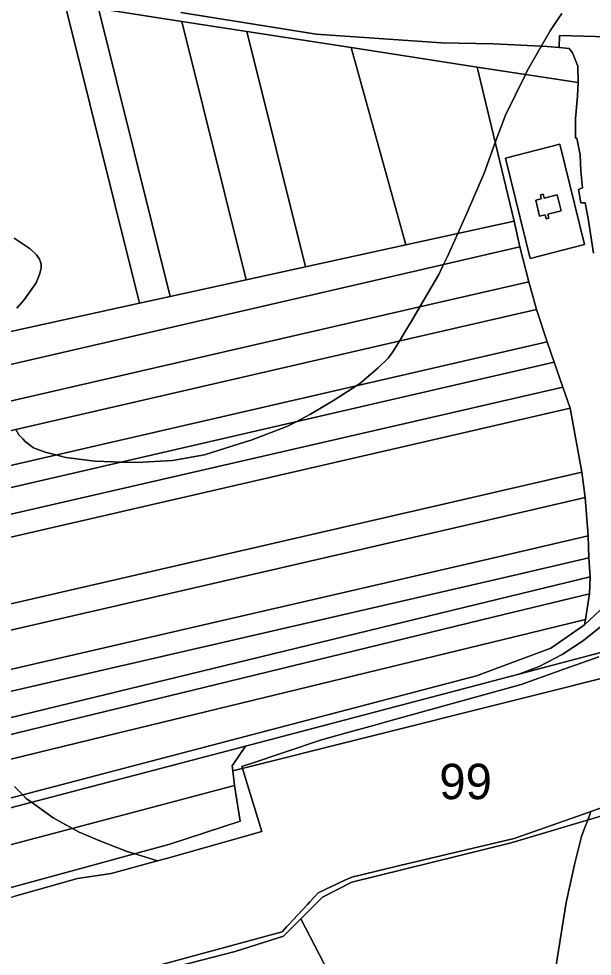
# Model space of a CAD drawing. Extents: x -521939 to -516426, y -1197857 to -1189551.
# Drawn here: x -519336.3 to -519093.3, y -1193402.1 to -1193004.4 of the extents above; entities that cross this region are included whole.
import ezdxf

# ---------------------------------------------------------------- set-up
doc = ezdxf.new("R2010")
doc.units = 0
for name, color, linetype in [('95560013', 7, 'Continuous'), ('95610013', 7, 'Continuous'), ('95620013', 7, 'Continuous'), ('95640013', 7, 'Continuous'), ('95660013', 7, 'Continuous')]:
    doc.layers.add(name, color=color, linetype=linetype)

msp = doc.modelspace()

# ---------------------------------------------------------------- linework, layer by layer
at = {"layer": '95560013'}
for points in [[(-519342.22, -1193137.6), (-519379.4, -1192988.21), (-519316.79, -1192997.86), (-519285.18, -1193125.04)], [(-519316.79, -1192997.86), (-519302.57, -1193000.06), (-519272.23, -1193122.17), (-519285.18, -1193125.04)], [(-519302.57, -1193000.06), (-519267.23, -1193005.51), (-519239.97, -1193115.13), (-519272.23, -1193122.17)], [(-519239.97, -1193115.13), (-519267.23, -1193005.51), (-519239.74, -1193009.74), (-519214.83, -1193109.59)], [(-519214.83, -1193109.59), (-519239.74, -1193009.74), (-519195.48, -1193016.56), (-519172.33, -1193100.26)], [(-519195.48, -1193016.56), (-519142.04, -1193024.85), (-519126.47, -1193090.19), (-519172.33, -1193100.26)], [(-519239.97, -1193115.13), (-519214.83, -1193109.59), (-519172.33, -1193100.26), (-519126.47, -1193090.19), (-519123.99, -1193101.18), (-519170.84, -1193111.98), (-519345.53, -1193152.25), (-519523.43, -1193193.26), (-519526.25, -1193178), (-519492.9, -1193170.62), (-519467.25, -1193165.07), (-519449.34, -1193161.11), (-519428.65, -1193156.57), (-519408.54, -1193152.16), (-519391.66, -1193148.43), (-519367.63, -1193143.15), (-519342.22, -1193137.6), (-519285.18, -1193125.04), (-519272.23, -1193122.17)], [(-519123.99, -1193101.18), (-519120.24, -1193115.95), (-519170.81, -1193127.61), (-519345.68, -1193167.93), (-519520.68, -1193208.28), (-519523.43, -1193193.26), (-519345.53, -1193152.25), (-519170.84, -1193111.98)], [(-519120.24, -1193115.95), (-519116.96, -1193127.76), (-519164.22, -1193138.66), (-519341.25, -1193179.49), (-519518.41, -1193220.35), (-519520.68, -1193208.28), (-519345.68, -1193167.93), (-519170.81, -1193127.61)], [(-519518.41, -1193220.35), (-519341.25, -1193179.49), (-519164.22, -1193138.66), (-519116.96, -1193127.76), (-519112.38, -1193141.37), (-519168.8, -1193154.38), (-519342.31, -1193194.39), (-519515.82, -1193234.4)], [(-519515.82, -1193234.4), (-519342.31, -1193194.39), (-519168.8, -1193154.38), (-519112.38, -1193141.37), (-519109.38, -1193150.03), (-519158.4, -1193161.36), (-519330.9, -1193201.23), (-519514.13, -1193243.58)], [(-519514.13, -1193243.58), (-519330.9, -1193201.23), (-519158.4, -1193161.36), (-519109.38, -1193150.03), (-519105.74, -1193160.59), (-519151.16, -1193171.07), (-519331.67, -1193212.72), (-519512.05, -1193254.34)], [(-519512.05, -1193254.34), (-519331.67, -1193212.72), (-519151.16, -1193171.07), (-519105.74, -1193160.59), (-519102.67, -1193169.53), (-519158.33, -1193182.37), (-519334.24, -1193222.95), (-519510.02, -1193263.5)], [(-519102.67, -1193169.53), (-519097.75, -1193196.73), (-519152.16, -1193209.3), (-519327.38, -1193249.78), (-519502.6, -1193290.26), (-519510.02, -1193263.5), (-519334.24, -1193222.95), (-519158.33, -1193182.37)], [(-519502.6, -1193290.26), (-519327.38, -1193249.78), (-519152.16, -1193209.3), (-519097.75, -1193196.73), (-519096.25, -1193207.51), (-519145.49, -1193218.89), (-519324.45, -1193260.25), (-519498.91, -1193300.57)], [(-519498.91, -1193300.57), (-519324.45, -1193260.25), (-519145.49, -1193218.89), (-519096.25, -1193207.51), (-519095.03, -1193223.76), (-519135.65, -1193233.16), (-519314.81, -1193274.62), (-519492.76, -1193315.8)], [(-519492.76, -1193315.8), (-519314.81, -1193274.62), (-519135.65, -1193233.16), (-519095.03, -1193223.76), (-519094.71, -1193233.1), (-519131.02, -1193241.48), (-519310.1, -1193282.81), (-519488.92, -1193324.08)], [(-519094.71, -1193233.1), (-519094.15, -1193241.05), (-519147.76, -1193254.09), (-519314.51, -1193294.65), (-519483.11, -1193335.66), (-519488.92, -1193324.08), (-519310.1, -1193282.81), (-519131.02, -1193241.48)], [(-519094.15, -1193241.05), (-519094.48, -1193248.3), (-519130.26, -1193257.01), (-519304.97, -1193299.54), (-519479.68, -1193342.07), (-519483.11, -1193335.66), (-519314.51, -1193294.65), (-519147.76, -1193254.09)], [(-519479.68, -1193342.07), (-519304.97, -1193299.54), (-519130.26, -1193257.01), (-519094.48, -1193248.3), (-519096.2, -1193259.2), (-519126.3, -1193266.53), (-519300.33, -1193308.91), (-519474.36, -1193351.29)], [(-519096.2, -1193259.2), (-519096.57, -1193261.51), (-519110.89, -1193271.43), (-519142.38, -1193283.13), (-519283.48, -1193320.18), (-519459.16, -1193366.31), (-519466.55, -1193363.58), (-519474.36, -1193351.29), (-519300.33, -1193308.91), (-519126.3, -1193266.53)], [(-519458.56, -1193374.41), (-519456.94, -1193369.86), (-519284.36, -1193324.57), (-519240.31, -1193313.01), (-519245.94, -1193321.3), (-519245.64, -1193323.44), (-519244.89, -1193329.7), (-519279.58, -1193338.87), (-519451.29, -1193384.26)], [(-519244.89, -1193329.7), (-519242.56, -1193344.82), (-519272.27, -1193354.6), (-519363, -1193379.33), (-519414.21, -1193393.4), (-519436.58, -1193400.77), (-519451.29, -1193384.26), (-519279.58, -1193338.87)]]:
    msp.add_lwpolyline(points, close=True, dxfattribs=at)
at = {"layer": '95610013'}
msp.add_lwpolyline([(-519216.77, -1193386.17), (-519201.14, -1193416.51), (-519380.85, -1193458.26), (-519400.65, -1193437.87), (-519323.14, -1193420.3), (-519244.63, -1193400.06), (-519224.13, -1193393.57)], close=True, dxfattribs=at)
at = {"layer": '95620013'}
for points in [[(-519051.78, -1193263.19), (-519124.36, -1193282.37), (-519115.87, -1193279.15), (-519106.02, -1193274.02), (-519097.04, -1193268.18), (-519089.06, -1193261.77), (-519081.5, -1193254.17), (-519075.4, -1193246.52), (-519067.67, -1193235.07), (-519065.42, -1193233.19), (-519057.96, -1193237.27)], [(-519124.36, -1193282.37), (-519051.78, -1193263.19), (-519049.8, -1193274.26), (-519072.06, -1193279.85), (-519245.64, -1193323.44), (-519245.94, -1193321.3), (-519240.31, -1193313.01)], [(-519049.8, -1193274.26), (-519040.03, -1193304.65), (-519061.29, -1193334.23), (-519127.73, -1193353.98), (-519195.16, -1193370.61), (-519207.67, -1193377.01), (-519216.77, -1193386.17), (-519224.13, -1193393.57), (-519244.63, -1193400.06), (-519323.14, -1193420.3), (-519400.65, -1193437.87), (-519436.58, -1193400.77), (-519414.21, -1193393.4), (-519363, -1193379.33), (-519272.27, -1193354.6), (-519242.56, -1193344.82), (-519244.89, -1193329.7), (-519245.64, -1193323.44), (-519072.06, -1193279.85)]]:
    msp.add_lwpolyline(points, close=True, dxfattribs=at)
at = {"layer": '95640013'}
for points in [[(-519267.67, -1193001.68), (-519210.29, -1193010.83), (-519157.21, -1193014.6), (-519135.18, -1193014.94), (-519126.21, -1193015.42), (-519112.45, -1193016.14), (-519107.3, -1193016.61), (-519103.14, -1193016.99), (-519101.64, -1193018.75), (-519099.43, -1193024.53), (-519099.27, -1193031.44), (-519142.04, -1193024.85), (-519195.48, -1193016.56), (-519239.74, -1193009.74), (-519267.23, -1193005.51), (-519302.57, -1193000.06)], [(-519081.82, -1193012.11), (-519107.14, -1193011.48), (-519107.3, -1193016.61), (-519112.45, -1193016.14), (-519126.21, -1193015.42), (-519135.18, -1193014.94), (-519157.21, -1193014.6), (-519210.29, -1193010.83), (-519267.67, -1193001.68)], [(-519092.79, -1193103.81), (-519094.99, -1193089.06), (-519096.34, -1193082.48), (-519098.12, -1193082.46), (-519099.18, -1193076.82), (-519097.38, -1193076.11), (-519098.14, -1193068.98), (-519098.49, -1193062.14), (-519099.79, -1193055.02), (-519100.47, -1193055.02), (-519100.42, -1193046.7), (-519099.54, -1193037.16), (-519099.27, -1193031.44), (-519099.43, -1193024.53), (-519101.64, -1193018.75), (-519103.14, -1193016.99), (-519107.3, -1193016.61), (-519107.14, -1193011.48), (-519081.82, -1193012.11)], [(-519083.46, -1193249.19), (-519096.57, -1193261.51), (-519096.2, -1193259.2), (-519094.48, -1193248.3), (-519094.15, -1193241.05), (-519094.71, -1193233.1), (-519095.03, -1193223.76), (-519096.25, -1193207.51), (-519097.75, -1193196.73), (-519102.67, -1193169.53), (-519105.74, -1193160.59), (-519109.38, -1193150.03), (-519112.38, -1193141.37), (-519116.96, -1193127.76), (-519120.24, -1193115.95), (-519123.99, -1193101.18), (-519126.47, -1193090.19), (-519142.04, -1193024.85), (-519099.27, -1193031.44), (-519099.54, -1193037.16), (-519100.42, -1193046.7), (-519100.47, -1193055.02), (-519099.79, -1193055.02), (-519098.49, -1193062.14), (-519098.14, -1193068.98), (-519097.38, -1193076.11), (-519099.18, -1193076.82), (-519098.12, -1193082.46), (-519096.34, -1193082.48), (-519094.99, -1193089.06), (-519092.79, -1193103.81)]]:
    msp.add_lwpolyline(points, dxfattribs=at)
for points in [[(-519130.14, -1193063.54), (-519107.08, -1193057.58), (-519096.56, -1193100.18), (-519119.61, -1193106.06)], [(-519130.14, -1193063.54), (-519119.61, -1193106.06), (-519096.56, -1193100.18), (-519107.08, -1193057.58)], [(-519115.28, -1193079.08), (-519114.18, -1193078.8), (-519113.75, -1193080.45), (-519108.18, -1193079.1), (-519106.53, -1193085.86), (-519112.13, -1193087.24), (-519111.74, -1193088.97), (-519112.85, -1193089.23), (-519113.24, -1193087.5), (-519115.62, -1193088.05), (-519117.25, -1193081.31), (-519114.91, -1193080.73)], [(-519114.91, -1193080.73), (-519117.25, -1193081.31), (-519115.62, -1193088.05), (-519113.24, -1193087.5), (-519112.85, -1193089.23), (-519111.74, -1193088.97), (-519112.13, -1193087.24), (-519106.53, -1193085.86), (-519108.18, -1193079.1), (-519113.75, -1193080.45), (-519114.18, -1193078.8), (-519115.28, -1193079.08)], [(-519110.89, -1193271.43), (-519096.57, -1193261.51), (-519083.46, -1193249.19), (-519064.08, -1193221.98), (-519063.8, -1193218.73), (-519061.2, -1193228.34), (-519057.96, -1193237.27), (-519065.42, -1193233.19), (-519067.67, -1193235.07), (-519075.4, -1193246.52), (-519081.5, -1193254.17), (-519089.06, -1193261.77), (-519097.04, -1193268.18), (-519106.02, -1193274.02), (-519115.87, -1193279.15), (-519124.36, -1193282.37), (-519240.31, -1193313.01), (-519284.36, -1193324.57), (-519456.94, -1193369.86), (-519458.56, -1193374.41), (-519466.55, -1193363.58), (-519459.16, -1193366.31), (-519283.48, -1193320.18), (-519142.38, -1193283.13)], [(-519110.84, -1193580.01), (-519128.68, -1193547.96), (-519143.89, -1193520.55), (-519162.86, -1193486.08), (-519175.78, -1193463.01), (-519186.96, -1193442.78), (-519201.14, -1193416.51), (-519216.77, -1193386.17), (-519207.67, -1193377.01), (-519195.16, -1193370.61), (-519127.73, -1193353.98), (-519061.29, -1193334.23), (-519040.03, -1193304.65), (-519037.03, -1193315.32), (-519029.64, -1193352.06), (-519013.6, -1193412.23), (-518995.72, -1193458.59), (-518983.73, -1193485.98), (-518969.16, -1193519.14), (-518956.05, -1193564.77), (-518954.36, -1193589.13), (-519083.02, -1193619.12), (-519102.82, -1193594.23)]]:
    msp.add_lwpolyline(points, close=True, dxfattribs=at)
at = {"layer": '95660013'}
for points in [[(-519106.24, -1193002.19), (-519107.69, -1193004.38), (-519111.1, -1193009.53), (-519115.32, -1193016.87), (-519120.83, -1193026.45), (-519121.6, -1193028), (-519130.11, -1193045.23), (-519134.4, -1193056.9), (-519139.15, -1193069.8), (-519146.33, -1193086.49), (-519150.29, -1193095.42), (-519153.52, -1193102.72), (-519154.86, -1193105.52), (-519156.35, -1193108.64), (-519158.39, -1193112.92), (-519166.34, -1193126.58), (-519169.86, -1193132.62), (-519172.58, -1193137.1), (-519175.05, -1193141.16), (-519177.75, -1193145.6), (-519178.92, -1193147.17), (-519179.83, -1193148.39), (-519184.12, -1193152.56), (-519192, -1193159.28), (-519193.12, -1193159.99), (-519203.01, -1193166.24), (-519212.64, -1193172.15), (-519218.76, -1193175.31), (-519222.72, -1193177.36), (-519237.9, -1193183.16), (-519240.32, -1193183.91), (-519257.61, -1193189.3), (-519271.17, -1193191.74), (-519286.24, -1193192.66), (-519292.89, -1193192.45), (-519296.16, -1193192.34), (-519304.09, -1193192.09), (-519316.38, -1193190.46), (-519320.65, -1193189.39), (-519325.19, -1193188.26), (-519330.05, -1193186.41), (-519333.65, -1193183.74), (-519334.67, -1193182.63), (-519336.31, -1193180.84), (-519337.56, -1193178.64)], [(-519337.56, -1193178.64), (-519336.31, -1193180.84), (-519334.67, -1193182.63), (-519333.65, -1193183.74), (-519330.05, -1193186.41), (-519325.19, -1193188.26), (-519320.65, -1193189.39), (-519316.38, -1193190.46), (-519304.09, -1193192.09), (-519296.16, -1193192.34), (-519292.89, -1193192.45), (-519286.24, -1193192.66), (-519271.17, -1193191.74), (-519257.61, -1193189.3), (-519240.32, -1193183.91), (-519237.9, -1193183.16), (-519222.72, -1193177.36), (-519218.76, -1193175.31), (-519212.64, -1193172.15), (-519203.01, -1193166.24), (-519193.12, -1193159.99), (-519192, -1193159.28), (-519184.12, -1193152.56), (-519179.83, -1193148.39), (-519178.92, -1193147.17), (-519177.75, -1193145.6), (-519175.05, -1193141.16), (-519172.58, -1193137.1), (-519169.86, -1193132.62), (-519166.34, -1193126.58), (-519158.39, -1193112.92), (-519156.35, -1193108.64), (-519154.86, -1193105.52), (-519153.52, -1193102.72), (-519150.29, -1193095.42), (-519146.33, -1193086.49), (-519139.15, -1193069.8), (-519134.4, -1193056.9), (-519130.11, -1193045.23), (-519121.6, -1193028), (-519120.83, -1193026.45), (-519115.32, -1193016.87), (-519111.1, -1193009.53), (-519107.69, -1193004.38), (-519106.24, -1193002.19)], [(-519337.11, -1193127.08), (-519333.99, -1193123.58), (-519329.01, -1193116.4), (-519327.5, -1193112.92), (-519326.96, -1193110.74), (-519326.81, -1193110.14), (-519326.81, -1193108.51), (-519327.5, -1193106.31), (-519328.78, -1193104.57), (-519331.56, -1193102.02), (-519338.28, -1193097.5)], [(-519338.28, -1193097.5), (-519331.56, -1193102.02), (-519328.78, -1193104.57), (-519327.5, -1193106.31), (-519326.81, -1193108.51), (-519326.81, -1193110.14), (-519326.96, -1193110.74), (-519327.5, -1193112.92), (-519329.01, -1193116.4), (-519333.99, -1193123.58), (-519337.11, -1193127.08)], [(-519394.68, -1193433.31), (-519423.63, -1193400.22), (-519411.2, -1193396.08), (-519363.33, -1193383.76), (-519337.96, -1193376.56), (-519334.53, -1193375.59), (-519311.43, -1193369.04), (-519297.24, -1193367.04), (-519277.57, -1193361.67), (-519273.69, -1193360.61), (-519233.36, -1193349.16), (-519233.91, -1193347.34), (-519234.47, -1193345.5), (-519241.51, -1193322.4), (-519241.77, -1193321.56), (-519238.87, -1193320.59), (-519238.26, -1193320.39), (-519208.11, -1193310.3), (-519197.48, -1193307.35), (-519185.97, -1193304.16), (-519179.05, -1193302.24), (-519123.5, -1193286.83), (-519106.86, -1193280.88), (-519090.5, -1193275.02)], [(-519090.5, -1193275.02), (-519106.86, -1193280.88), (-519123.5, -1193286.83), (-519179.05, -1193302.24), (-519185.97, -1193304.16), (-519197.48, -1193307.35), (-519208.11, -1193310.3), (-519238.26, -1193320.39), (-519238.87, -1193320.59), (-519241.77, -1193321.56), (-519241.51, -1193322.4), (-519234.47, -1193345.5), (-519233.91, -1193347.34), (-519233.36, -1193349.16), (-519273.69, -1193360.61), (-519277.57, -1193361.67), (-519282.49, -1193360.11), (-519286.15, -1193358.95), (-519287.11, -1193358.65), (-519290.76, -1193357.49), (-519302, -1193353.09), (-519310.7, -1193349.38), (-519313.51, -1193347.84), (-519321.71, -1193343.35), (-519330.87, -1193336.78), (-519333.18, -1193335.12), (-519334.65, -1193333.62), (-519338.14, -1193330.05)], [(-519338.14, -1193330.05), (-519334.65, -1193333.62), (-519333.18, -1193335.12), (-519330.87, -1193336.78), (-519321.71, -1193343.35), (-519313.51, -1193347.84), (-519310.7, -1193349.38), (-519302, -1193353.09), (-519290.76, -1193357.49), (-519287.11, -1193358.65), (-519286.15, -1193358.95), (-519282.49, -1193360.11), (-519277.57, -1193361.67), (-519297.24, -1193367.04), (-519311.43, -1193369.04), (-519334.53, -1193375.59), (-519337.96, -1193376.56)], [(-519071.1, -1193332.76), (-519093.85, -1193340.71), (-519094.2, -1193340.83), (-519126.44, -1193352.09), (-519174.87, -1193363.64), (-519195.25, -1193368.5), (-519198.12, -1193369.85), (-519209.52, -1193375.2), (-519213, -1193378.98), (-519214, -1193380.06), (-519222.11, -1193388.88), (-519222.67, -1193389.48), (-519224.69, -1193391.68), (-519246.07, -1193397.49), (-519324.52, -1193418.94)], [(-519111.37, -1193423.59), (-519104.42, -1193379.31), (-519100.71, -1193362.62), (-519097.93, -1193351.26), (-519096.46, -1193347.48), (-519095.24, -1193344.32), (-519094.3, -1193341.89), (-519093.85, -1193340.71), (-519071.1, -1193332.76)], [(-519324.52, -1193418.94), (-519246.07, -1193397.49), (-519224.69, -1193391.68), (-519222.67, -1193389.48), (-519222.11, -1193388.88), (-519214, -1193380.06), (-519213, -1193378.98), (-519209.52, -1193375.2), (-519198.12, -1193369.85), (-519195.25, -1193368.5), (-519174.87, -1193363.64), (-519126.44, -1193352.09), (-519094.2, -1193340.83), (-519093.85, -1193340.71), (-519094.3, -1193341.89), (-519095.24, -1193344.32), (-519096.46, -1193347.48), (-519097.93, -1193351.26), (-519100.71, -1193362.62), (-519104.42, -1193379.31), (-519111.37, -1193423.59)]]:
    msp.add_lwpolyline(points, dxfattribs=at)

# ---------------------------------------------------------------- texts
msp.add_text('99', height=15, rotation=360, dxfattribs=at).set_placement((-519158.15, -1193335.44))

doc.saveas('drawing.dxf')
